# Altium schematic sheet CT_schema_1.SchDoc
size 592 x 258 mm
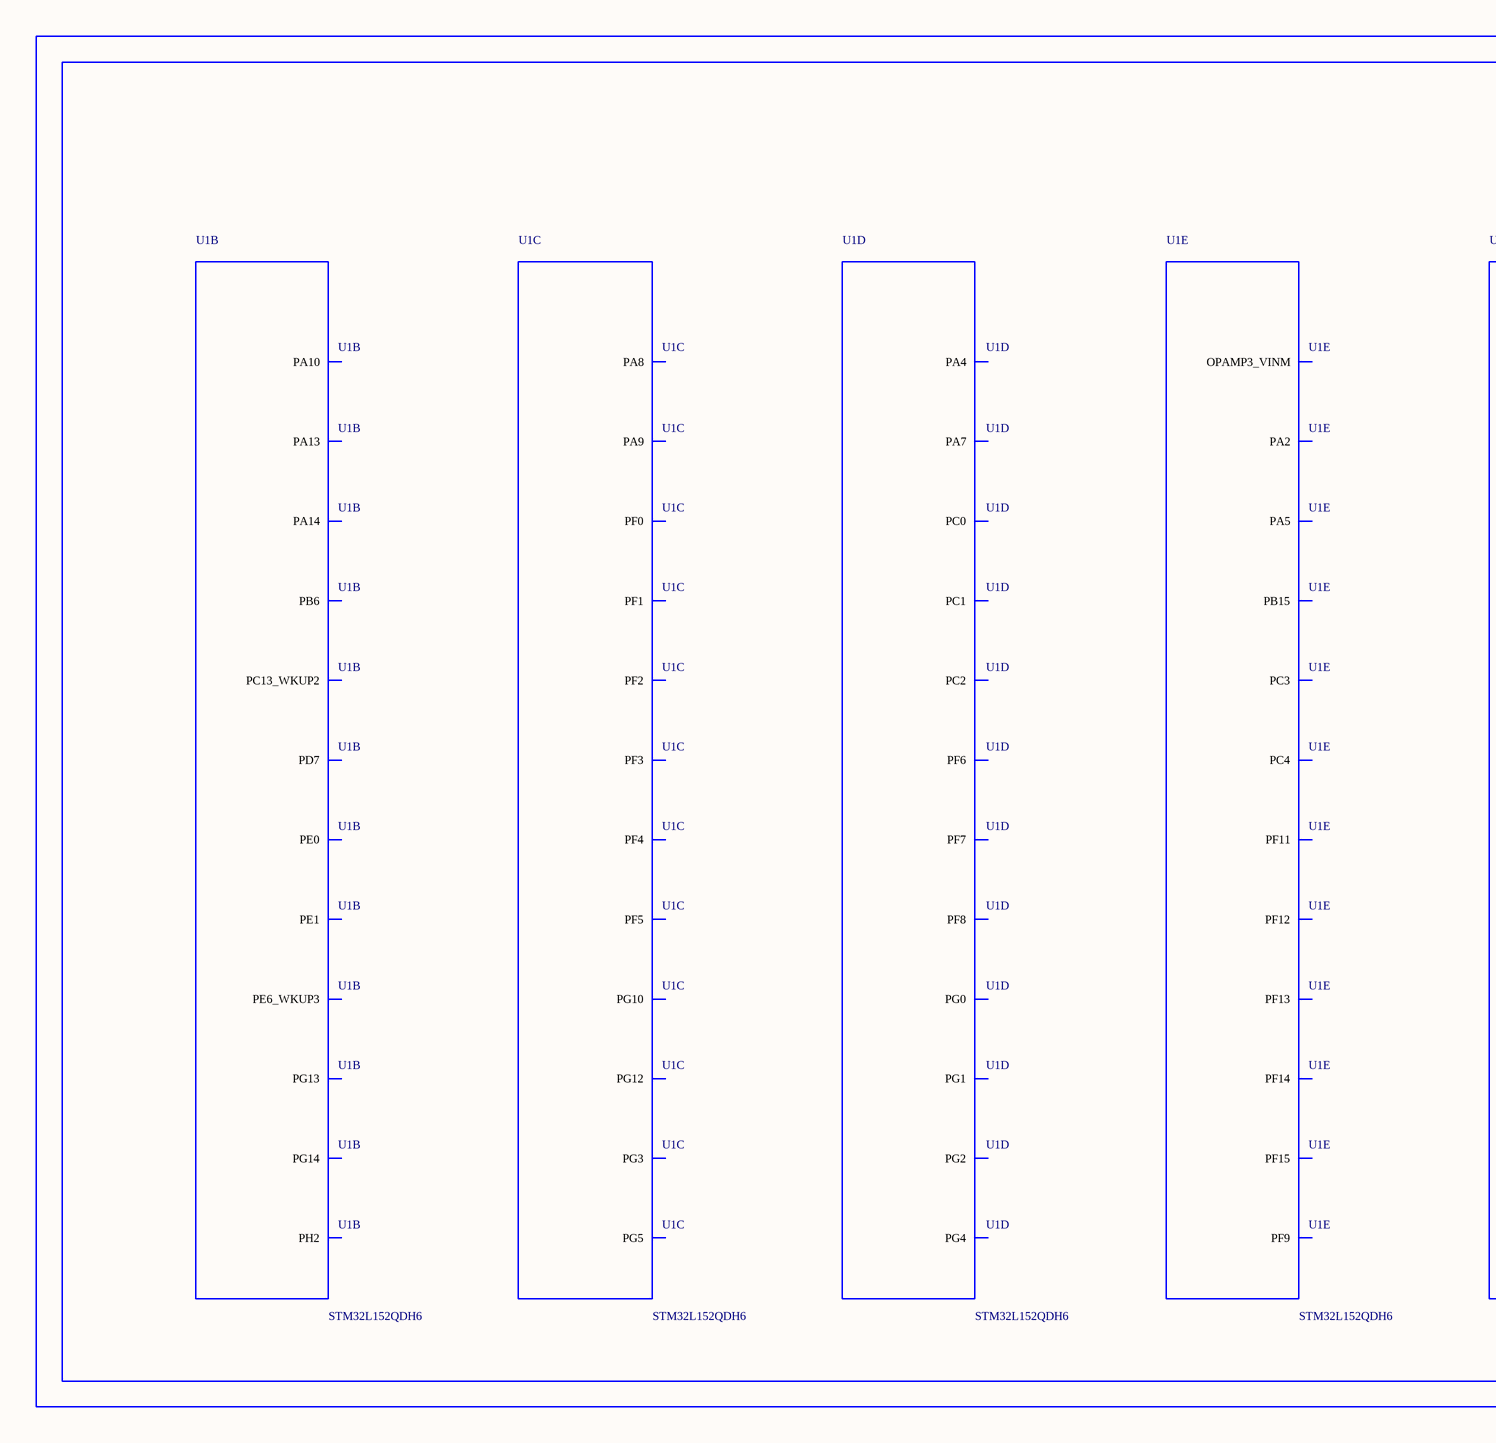
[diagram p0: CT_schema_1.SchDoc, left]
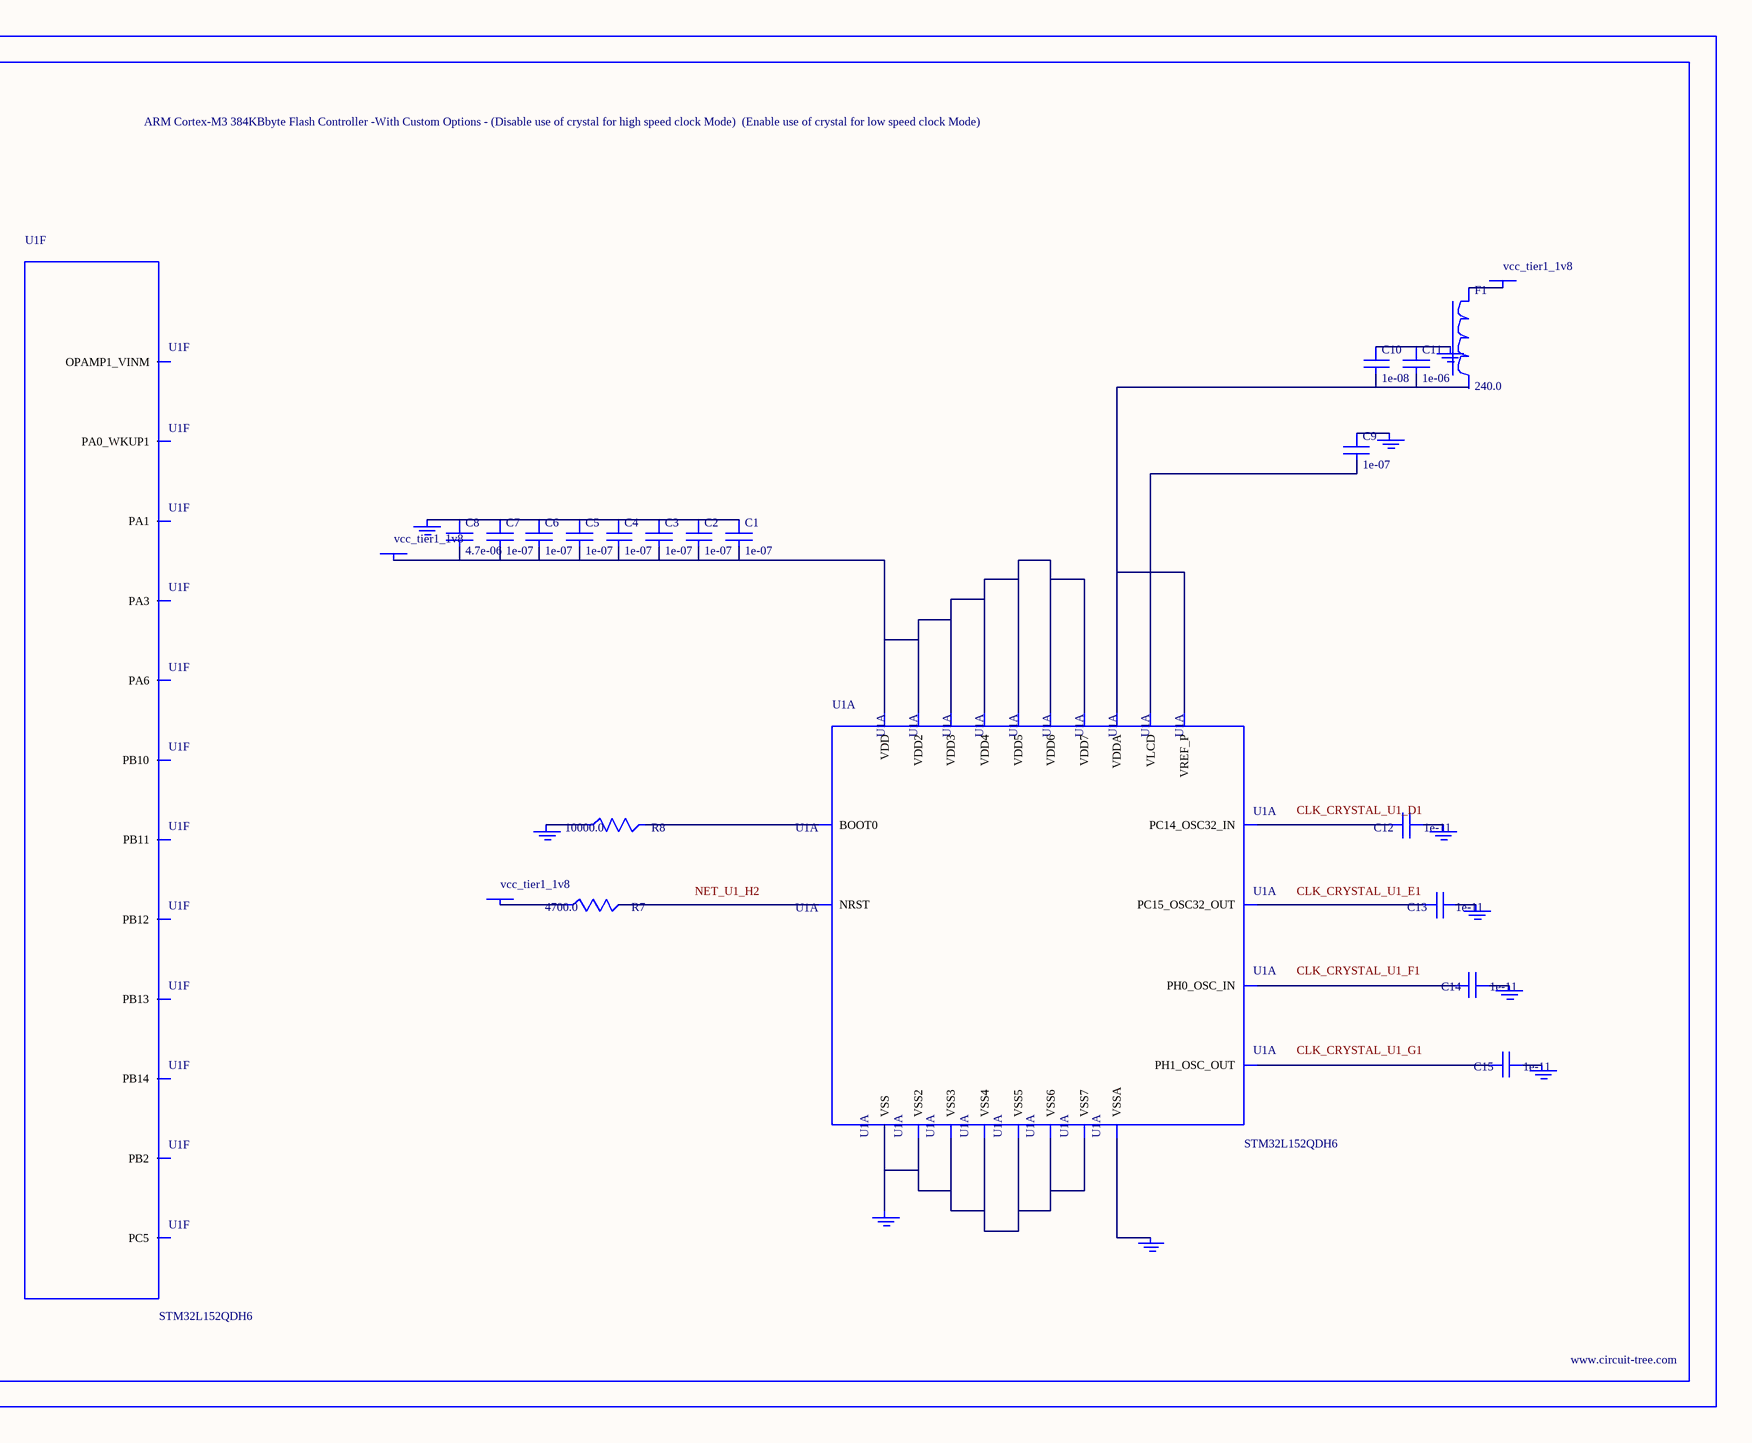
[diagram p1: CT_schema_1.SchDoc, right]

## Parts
BORDER0  (no value)
C1  1e-07  [C0603]
C2  1e-07  [C0603]
C3  1e-07  [C0603]
C4  1e-07  [C0603]
C5  1e-07  [C0603]
C6  1e-07  [C0603]
C7  1e-07  [C0603]
C8  4.7e-06  [C0603]
C9  1e-07  [C0603]
C10  1e-08  [C0603]
C11  1e-06  [C0603]
C12  1e-11  [C0402]
C13  1e-11  [C0402]
C14  1e-11  [C0402]
C15  1e-11  [C0402]
F1  240.0  [L0603]
GND_INSTANCE_0_0  (no value)
GND_INSTANCE_0_1  (no value)
GND_INSTANCE_0_2  (no value)
GND_INSTANCE_0_3  (no value)
GND_INSTANCE_0_4  (no value)
GND_INSTANCE_0_5  (no value)
GND_INSTANCE_0_6  (no value)
GND_INSTANCE_0_7  (no value)
GND_INSTANCE_0_8  (no value)
GND_INSTANCE_0_9  (no value)
POWER_INSTANCE_0_0  vcc_tier1_1v8
POWER_INSTANCE_0_1  vcc_tier1_1v8
POWER_INSTANCE_0_2  vcc_tier1_1v8
R7  4700.0  [R0603]
R8  10000.0  [R0603]
U1  STM32L152QDH6  [UFBGA132]  (parts A,B,C,D,E,F of 11)

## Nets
NetC1_1: C1.1 C2.1 C3.1 C4.1 C5.1 C6.1 C7.1 C8.1 GND_INSTANCE_0_1.0(GND)
NetC1_2: C1.2 C2.2 C3.2 C4.2 C5.2 C6.2 C7.2 C8.2 POWER_INSTANCE_0_1.0(PWR) U1.C4(VDD) U1.G2(VDD4) U1.G6(VDD5) U1.G7(VDD6) U1.G11(VDD2) U1.G12(VDD3) U1.H3(VDD7)
NetC9_1: C9.1 GND_INSTANCE_0_2.0(GND)
NetC9_2: C9.2 U1.E2(VLCD)
NetC10_1: C10.1 C11.1 GND_INSTANCE_0_0.0(GND)
NetC10_2: C10.2 C11.2 U1.L1(VREF_P) U1.M1(VDDA)
NetC12_1: C12.1 GND_INSTANCE_0_4.0(GND)
NetC12_2: C12.2 U1.D1(PC14_OSC32_IN)
NetC13_1: C13.1 GND_INSTANCE_0_5.0(GND)
NetC13_2: C13.2 U1.E1(PC15_OSC32_OUT)
NetC14_1: C14.1 GND_INSTANCE_0_6.0(GND)
NetC14_2: C14.2 U1.F1(PH0_OSC_IN)
NetC15_1: C15.1 GND_INSTANCE_0_7.0(GND)
NetC15_2: C15.2 U1.G1(PH1_OSC_OUT)
NetF1_1: F1.1 POWER_INSTANCE_0_0.0(PWR)
NetGND_INSTANCE_0_3_0: GND_INSTANCE_0_3.0(GND) R8.1
NetGND_INSTANCE_0_8_0: GND_INSTANCE_0_8.0(GND) U1.J1(VSSA)
NetGND_INSTANCE_0_9_0: GND_INSTANCE_0_9.0(GND) U1.D3(VSS) U1.E3(VSS2) U1.F2(VSS5) U1.F6(VSS6) U1.F7(VSS7) U1.F11(VSS3) U1.F12(VSS4)
NetPOWER_INSTANCE_0_2_0: POWER_INSTANCE_0_2.0(PWR) R7.1
NetR7_2: R7.2 U1.H2(NRST)
NetR8_2: R8.2 U1.A4(BOOT0)

Not connected (* = marked no-connect by the designer): F1 2; U1 A2(PE1) A5(PD7) A10(PA14) A11(PA13) B5(PB6) C1(PC13_WKUP2) C3(PE0) C6(PG14) C7(PG13) C11(PH2) C12(PA10) D2(PE6_WKUP3) D4(PF2) D5(PF1) D6(PF0) D7(PG12) D8(PG10) D10(PA9) D11(PA8) E4(PF3) E9(PG5) F3(PF4) F4(PF5) F9(PG3) F10(PG4) G3(PF6) G4(PF7) G9(PG1) G10(PG2) H1(PC0) H4(PF8) H9(PG0) J2(PC1) J3(PC2) J4(PA4) J5(PA7) J6(PF9) J7(PF12) J8(PF14) J9(PF15) K1(OPAMP3_VINM) K2(PC3) K3(PA2) K4(PA5) K5(PC4) K6(PF11) K7(PF13) K10(PB15) K11(PB14) K12(PB13) L2(PA0_WKUP1) L3(PA3) L4(PA6) L5(PC5) L6(PB2) L10(PB10) L11(PB11) L12(PB12) M2(PA1) M3(OPAMP1_VINM)

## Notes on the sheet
- Labels drawn without touching a wire or pin: CLK_CRYSTAL_U1_D1, CLK_CRYSTAL_U1_E1, CLK_CRYSTAL_U1_F1, CLK_CRYSTAL_U1_G1, NET_U1_H2

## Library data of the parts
BORDER0 = BORDER_PAGE0
C1-C7 C9 = 06035C104K4Z2A
C8 = GRM188R6YA475KE15D
C10 = 06035C103K4Z2A
C11 = C0603C105K3RACTU
C12-C15 = C0402C100K3GACTU
F1 = Z0603C241ASMST
GND_INSTANCE_0_0-GND_INSTANCE_0_9 = GND
POWER_INSTANCE_0_0-POWER_INSTANCE_0_2 = PWR
R7 = RC0603JR-074K7L
R8 = RC0603JR-0710KL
